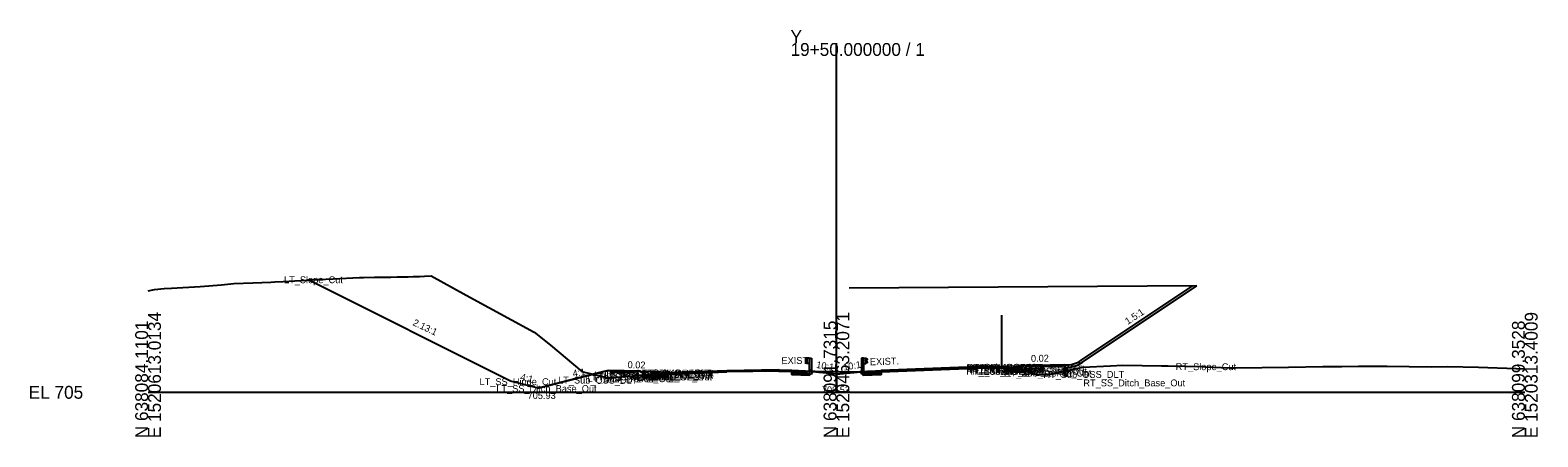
# Model space of a CAD drawing. Extents: x -26 to 303, y -10 to 5039.
# Drawn here: x -25.7 to 302.8, y 2990.3 to 3078.8 of the extents above; entities that cross this region are included whole.
import ezdxf

# ---------------------------------------------------------------- set-up
doc = ezdxf.new("R2010")
doc.units = 0
for name, color, linetype in [('Default', 7, 'Continuous'), ('Exist Cross Section Cell', 7, 'Continuous'), ('Exist XS Center Line Elevation Label', 7, 'Continuous'), ('Exist XS Ground Line', 7, 'Continuous'), ('Prop CMT Bridge Metal Rail', 7, 'Continuous'), ('Prop CMT Pvmt Course 1', 7, 'Continuous'), ('Prop CMT Pvmt Course 2', 7, 'Continuous'), ('Prop CMT Pvmt Course 3', 7, 'Continuous'), ('Prop CMT Pvmt Surface Shoulder', 7, 'Continuous'), ('Prop CMT Shld Paved Course 1', 7, 'Continuous'), ('Prop CMT Shld Paved Course 2', 7, 'Continuous'), ('Prop CMT Shld Paved Course 3', 7, 'Continuous'), ('Prop CMT Slope Grass', 7, 'Continuous'), ('Prop CMT Subgrade Earthwork', 7, 'Continuous'), ('Prop Conc 4in Sidewalk', 7, 'Continuous'), ('Prop XS Ditch Standard Text', 7, 'Continuous'), ('Prop XS Earthwork Shape', 7, 'Continuous'), ('Prop XS SE Text', 7, 'Continuous'), ('Prop XS Side Slope Text', 7, 'Continuous'), ('Scratch_Level_0', 7, 'Continuous'), ('Scratch_Level_1', 7, 'Continuous'), ('Scratch_Level_7', 7, 'Continuous'), ('Typical Curb CELL', 7, 'Continuous'), ('Typical Guardrail CELL', 7, 'Continuous'), ('Typical Shoulder Slope Information CELL', 7, 'Continuous')]:
    doc.layers.add(name, color=color, linetype=linetype)

# ---------------------------------------------------------------- blocks, each defined once
blk = doc.blocks.new('2_6 CURB RIGHT')
at = {"layer": 'Typical Curb CELL'}
for p, q in [((0, -0.58), (0, 0)), ((0, 0), (1.75, -0.07)), ((2, 0.17), (2, 0.18)), ((2.5, 0.42), (2.24, 0.42)), ((2.31, 0.08), (2.33, -0.01)), ((2.46, 0.04), (2.31, 0.08)), ((2.33, -0.01), (2.46, 0.04)), ((2.5, -0.58), (2.5, 0.42)), ((2.5, -0.58), (0, -0.58)), ((0.26, -0.34), (0.35, -0.22)), ((0.38, -0.34), (0.26, -0.34)), ((0.35, -0.22), (0.38, -0.34)), ((1.03, -0.39), (1.09, -0.28)), ((1.19, -0.36), (1.03, -0.39)), ((1.09, -0.28), (1.19, -0.36)), ((1.51, -0.34), (1.6, -0.22)), ((1.63, -0.34), (1.51, -0.34)), ((1.6, -0.22), (1.63, -0.34)), ((2.27, -0.39), (2.34, -0.28)), ((2.44, -0.36), (2.27, -0.39)), ((2.34, -0.28), (2.44, -0.36))]:
    blk.add_line(p, q, dxfattribs=at)
for centre in [(2.27, 0.34), (2.43, 0.12), (2.49, 0.31), (0.01, -0.55), (0.02, -0.25), (0.03, -0.15), (0.07, -0.39), (0.09, -0.18), (0.17, -0.34), (0.2, -0.06), (0.22, -0.58), (0.3, -0.14), (0.34, -0.04), (0.38, -0.51), (0.49, -0.1), (0.52, -0.21), (0.59, -0.53), (0.67, -0.29), (0.69, -0.12), (0.7, -0.45), (0.71, -0.07), (0.76, -0.56), (0.79, -0.26), (0.93, -0.5), (0.97, -0.1), (1.09, -0.15), (1.11, -0.54), (1.26, -0.55), (1.27, -0.25), (1.28, -0.15), (1.32, -0.39), (1.34, -0.18), (1.42, -0.34), (1.45, -0.1), (1.47, -0.58), (1.54, -0.14), (1.63, -0.51), (1.74, -0.1), (1.77, -0.21), (1.84, -0.53), (1.92, -0.29), (1.94, -0.12), (1.95, -0.45), (1.96, -0.07), (2.01, -0.56), (2.04, -0.26), (2.18, -0.5), (2.22, -0.1), (2.34, -0.15), (2.35, -0.54)]:
    blk.add_circle(centre, 0.00802, dxfattribs=at)
for centre, start, end in [((1.76, 0.17), 267.6155, 0), ((2.24, 0.18), 90, 180)]:
    blk.add_arc(centre, 0.24, start, end, dxfattribs=at)

msp = doc.modelspace()

# ---------------------------------------------------------------- linework, layer by layer
at = {"layer": 'Exist Cross Section Cell'}
for p, q in [((150, 3000), (150, 3076.04)), ((0, 3000), (150, 3000)), ((150, 3000), (300, 3000))]:
    msp.add_line(p, q, dxfattribs=at)
at = {"layer": 'Exist XS Ground Line'}
msp.add_lwpolyline([(0, 3022.1), (1.43, 3022.4), (3.51, 3022.57), (5.09, 3022.68), (11.37, 3023.04), (16.02, 3023.41), (18.66, 3023.67), (22.81, 3023.83), (26.72, 3024.01), (27.59, 3024.06), (29.41, 3024.15), (37.09, 3024.58), (40.3, 3024.73), (46.06, 3024.99), (46.46, 3025), (46.96, 3025.02), (49.31, 3025.03), (49.79, 3025.06), (50.16, 3025.06), (50.8, 3025.08), (51.96, 3025.09), (52.93, 3025.1), (54.29, 3025.12), (55.76, 3025.17), (56.68, 3025.17), (57.77, 3025.19), (59.18, 3025.2), (60.21, 3025.25), (61.66, 3025.35), (69.3, 3021.17), (84.1, 3013.07), (87.72, 3010.24), (94.49, 3004.51), (99.34, 3003.34), (100.25, 3003.11), (106.22, 3003.66), (110.41, 3004.05), (111.01, 3004.07), (111.75, 3004.1), (113.02, 3004.16), (113.87, 3004.21), (114.34, 3004.22), (115.53, 3004.26), (116.25, 3004.29), (118.03, 3004.36), (118.63, 3004.39), (120.53, 3004.46), (121, 3004.48), (123.03, 3004.56), (123.73, 3004.59), (125.77, 3004.68), (128, 3004.72), (130.52, 3004.76), (133.17, 3004.8), (135.75, 3004.84), (137.58, 3004.85), (138.16, 3004.85), (140.58, 3004.75), (141.18, 3004.74), (147.46, 3004.56), (150, 3004.53), (153.44, 3004.49), (155.46, 3004.48), (161.42, 3004.79), (162.01, 3004.82), (162.36, 3004.83), (163.11, 3004.86), (164.85, 3004.92), (165.58, 3004.94), (167.48, 3005.02), (168.09, 3005.05), (168.65, 3005.07), (170.59, 3005.13), (171.02, 3005.15), (173.25, 3005.24), (173.89, 3005.27), (175.58, 3005.3), (178.13, 3005.36), (179.44, 3005.38), (180.61, 3005.41), (182.94, 3005.44), (183.25, 3005.45), (185.05, 3005.47), (185.58, 3005.46), (187.15, 3005.37), (189.92, 3005.22), (192.94, 3004.07), (193.72, 3003.8), (194.17, 3003.8), (196.42, 3003.84), (197.48, 3004.07), (203.66, 3005.45), (209.73, 3005.77), (212.4, 3005.89), (220.85, 3005.78), (221.51, 3005.77), (222.28, 3005.75), (229.77, 3005.59), (230.37, 3005.53), (235.69, 3005.3), (236.12, 3005.32), (236.97, 3005.33), (248.53, 3005.48), (255.97, 3005.59), (260.11, 3005.64), (263.74, 3005.7), (264.76, 3005.68), (268.54, 3005.68), (269.98, 3005.72), (279.57, 3005.57), (283.14, 3005.61), (289.93, 3005.44), (298.08, 3005.2), (300, 3005.12)], dxfattribs=at)
at = {"layer": 'Prop CMT Bridge Metal Rail'}
for p, q in [((228.56, 3023.18), (152.76, 3022.7)), ((203.36, 3006.99), (227.65, 3023.18)), ((203.64, 3006.57), (228.56, 3023.18)), ((199.75, 3003.48), (199.75, 3005.98)), ((200.25, 3003.48), (199.75, 3003.48)), ((200.25, 3005.47), (200.25, 3003.48))]:
    msp.add_line(p, q, dxfattribs=at)
for radius, start in [(6, 267.4103), (6.5, 272.0181)]:
    msp.add_arc((200.02, 3011.97), radius, start, 303.8671, dxfattribs=at)
at = {"layer": 'Prop CMT Pvmt Course 1'}
for points in [[(113.25, 3004.18), (113.25, 3003.93)], [(113.25, 3003.93), (113.26, 3003.93)], [(113.26, 3003.93), (113.26, 3004.18)], [(140.25, 3004.49), (140.25, 3004.74)], [(159.75, 3004.49), (159.75, 3004.74)], [(186.74, 3005.16), (186.74, 3005.41)]]:
    msp.add_lwpolyline(points, dxfattribs=at)
at = {"layer": 'Prop CMT Pvmt Course 2'}
for points in [[(113.26, 3003.93), (113.25, 3003.93)], [(113.25, 3003.93), (113.25, 3003.68)], [(113.25, 3003.68), (113.26, 3003.68)], [(113.26, 3003.68), (113.26, 3003.93)], [(140.25, 3004.24), (140.25, 3004.49)], [(159.75, 3004.24), (159.75, 3004.49)]]:
    msp.add_lwpolyline(points, dxfattribs=at)
at = {"layer": 'Prop CMT Pvmt Course 3'}
for points in [[(113.26, 3003.68), (113.25, 3003.68)], [(113.25, 3003.68), (113.25, 3003.3)], [(113.25, 3003.3), (113.26, 3003.3)], [(113.26, 3003.3), (113.26, 3003.68)], [(140.25, 3003.87), (140.25, 3004.24)], [(140.26, 3003.87), (140.25, 3003.87)], [(146, 3004.1), (146.01, 3004.1)], [(159.74, 3003.86), (159.75, 3003.86)], [(159.75, 3003.86), (159.75, 3004.24)]]:
    msp.add_lwpolyline(points, dxfattribs=at)
at = {"layer": 'Prop CMT Pvmt Surface Shoulder'}
for p, q in [((137.45, 3004.86), (143.25, 3004.63)), ((187.75, 3005.37), (182.17, 3005.59))]:
    msp.add_line(p, q, dxfattribs=at)
for points in [[(126.1, 3004.7), (112.25, 3004.14)], [(137.45, 3004.86), (126.1, 3004.7)], [(156.75, 3004.63), (182.17, 3005.59)]]:
    msp.add_lwpolyline(points, dxfattribs=at)
at = {"layer": 'Prop CMT Shld Paved Course 1'}
for p, q in [((137.44, 3004.61), (126.1, 3004.45)), ((137.44, 3004.61), (140.25, 3004.5)), ((143.51, 3004.36), (143.25, 3004.63)), ((156.49, 3004.36), (156.75, 3004.63)), ((159.75, 3004.48), (182.17, 3005.34))]:
    msp.add_line(p, q, dxfattribs=at)
for points in [[(113.87, 3004.21), (112.25, 3004.14)], [(112.25, 3003.89), (113.26, 3003.93)], [(113.25, 3003.93), (113.25, 3004.18)], [(113.26, 3003.93), (126.11, 3004.45)], [(156.75, 3004.63), (162, 3004.82)], [(186.74, 3005.16), (182.17, 3005.34)], [(187.75, 3005.12), (186.74, 3005.16)]]:
    msp.add_lwpolyline(points, dxfattribs=at)
at = {"layer": 'Prop CMT Shld Paved Course 2'}
for p, q in [((143.77, 3004.1), (143.51, 3004.36)), ((156.23, 3004.1), (156.49, 3004.36))]:
    msp.add_line(p, q, dxfattribs=at)
for points in [[(113.26, 3003.93), (112.25, 3003.89)], [(112.25, 3003.64), (113.26, 3003.68)], [(113.25, 3003.68), (113.25, 3003.93)], [(140.25, 3004.5), (143.51, 3004.36)], [(143.77, 3004.1), (140.25, 3004.25)], [(156.23, 3004.1), (159.75, 3004.24)], [(159.75, 3004.49), (156.49, 3004.36)], [(186.74, 3005.16), (187.75, 3005.12)], [(187.75, 3004.87), (186.74, 3004.91)]]:
    msp.add_lwpolyline(points, dxfattribs=at)
at = {"layer": 'Prop CMT Shld Paved Course 3'}
for p, q in [((109.25, 3003.55), (108.82, 3003.13)), ((109.75, 3003.55), (109.25, 3003.55)), ((144.16, 3003.71), (143.77, 3004.1)), ((155.83, 3003.71), (156.23, 3004.1)), ((190.25, 3004.79), (190.75, 3004.79)), ((190.75, 3004.79), (191.18, 3004.36))]:
    msp.add_line(p, q, dxfattribs=at)
for points in [[(108.82, 3003.13), (113.26, 3003.3)], [(113.26, 3003.68), (112.25, 3003.64)], [(113.25, 3003.3), (113.25, 3003.68)], [(140.25, 3004.25), (143.77, 3004.1)], [(144.16, 3003.71), (140.25, 3003.87)], [(155.84, 3003.71), (159.75, 3003.86)], [(159.75, 3004.24), (156.23, 3004.1)], [(186.74, 3004.91), (187.75, 3004.87)], [(191.18, 3004.36), (186.74, 3004.53)]]:
    msp.add_lwpolyline(points, dxfattribs=at)
at = {"layer": 'Prop CMT Slope Grass'}
for p, q in [((84.97, 3000.93), (100.25, 3004.75)), ((100.25, 3004.75), (109.75, 3004.56)), ((150, 3003.95), (143.25, 3004.63)), ((150, 3003.95), (156.75, 3004.63)), ((199.75, 3005.98), (190.25, 3005.79))]:
    msp.add_line(p, q, dxfattribs=at)
msp.add_lwpolyline([(84.97, 3000.93), (78.97, 3002.43), (34.91, 3024.46)], dxfattribs=at)
at = {"layer": 'Prop CMT Subgrade Earthwork'}
for p, q in [((108.82, 3003.13), (107.34, 3004.61)), ((113.26, 3003.3), (113.26, 3004.18)), ((140.25, 3004.75), (140.25, 3003.87)), ((155.83, 3003.71), (155.08, 3004.46)), ((159.75, 3004.74), (159.75, 3003.86)), ((186.74, 3004.53), (186.74, 3005.41)), ((191.18, 3004.36), (192.65, 3005.83)), ((199.75, 3005.98), (199.75, 3004.58))]:
    msp.add_line(p, q, dxfattribs=at)
for points in [[(113.26, 3003.3), (108.82, 3003.13)], [(140.25, 3004.74), (140.25, 3003.87), (140.26, 3003.87)], [(140.25, 3003.87), (144.16, 3003.71)], [(144.16, 3003.71), (144.91, 3004.46)], [(159.75, 3003.86), (155.83, 3003.71)], [(159.75, 3004.74), (159.75, 3003.86), (159.74, 3003.86)], [(186.74, 3004.53), (191.18, 3004.36)]]:
    msp.add_lwpolyline(points, dxfattribs=at)
at = {"layer": 'Prop Conc 4in Sidewalk'}
for p, q in [((100.75, 3004.74), (100.75, 3004.41)), ((100.75, 3004.41), (105.75, 3004.31)), ((105.75, 3004.64), (105.75, 3004.31)), ((194.25, 3005.87), (194.25, 3005.53)), ((199.25, 3005.63), (194.25, 3005.53)), ((199.25, 3005.97), (199.25, 3005.63))]:
    msp.add_line(p, q, dxfattribs=at)
at = {"layer": 'Prop XS Earthwork Shape'}
for points in [[(57.77, 3025.19), (59.18, 3025.2), (60.21, 3025.25), (61.66, 3025.35), (69.3, 3021.17), (84.1, 3013.07), (87.72, 3010.24), (94.49, 3004.51), (96.93, 3003.92), (84.97, 3000.93), (78.97, 3002.43), (34.91, 3024.46), (37.09, 3024.58), (40.3, 3024.73), (46.06, 3024.99), (46.46, 3025), (46.96, 3025.02), (49.31, 3025.03), (49.79, 3025.06), (50.16, 3025.06), (50.8, 3025.08), (51.96, 3025.09), (52.93, 3025.1), (54.29, 3025.12), (55.76, 3025.17), (56.68, 3025.17)], [(100.25, 3003.11), (106.22, 3003.66), (108.12, 3003.83), (107.34, 3004.61), (100.25, 3004.75), (96.93, 3003.92), (99.34, 3003.34)], [(111.01, 3004.07), (111.75, 3004.1), (113.02, 3004.16), (113.26, 3004.17), (113.26, 3003.3), (108.82, 3003.13), (108.12, 3003.83), (110.41, 3004.05)], [(113.26, 3004.17), (113.26, 3004.18), (113.87, 3004.21)], [(123.03, 3004.56), (123.73, 3004.59), (125.77, 3004.68), (128, 3004.72), (130.52, 3004.76), (131.23, 3004.77), (126.1, 3004.7), (113.87, 3004.21), (114.34, 3004.22), (115.53, 3004.26), (116.25, 3004.29), (118.03, 3004.36), (118.63, 3004.39), (120.53, 3004.46), (121, 3004.48)], [(131.23, 3004.77), (133.17, 3004.8), (135.75, 3004.84), (136.39, 3004.84)], [(137.45, 3004.86), (137.58, 3004.85), (136.39, 3004.84)], [(153.44, 3004.49), (155.31, 3004.48), (155.08, 3004.46), (150, 3003.95), (144.91, 3004.46), (143.25, 3004.63), (140.25, 3004.74), (137.58, 3004.85), (138.16, 3004.85), (140.58, 3004.75), (141.18, 3004.74), (147.46, 3004.56), (150, 3004.53)], [(140.25, 3004.74), (140.26, 3003.87), (144.16, 3003.71), (144.91, 3004.46), (143.25, 3004.63)], [(155.08, 3004.46), (155.31, 3004.48), (155.46, 3004.48), (159.75, 3004.71), (159.74, 3003.86), (155.83, 3003.71)], [(173.25, 3005.24), (173.89, 3005.27), (175.58, 3005.3), (178.13, 3005.36), (179.44, 3005.38), (180.61, 3005.41), (182.94, 3005.44), (183.25, 3005.45), (185.05, 3005.47), (185.31, 3005.47), (182.17, 3005.59), (159.75, 3004.74), (159.75, 3004.71), (161.42, 3004.79), (162.01, 3004.82), (162.36, 3004.83), (163.11, 3004.86), (164.85, 3004.92), (165.58, 3004.94), (167.48, 3005.02), (168.09, 3005.05), (168.65, 3005.07), (170.59, 3005.13), (171.02, 3005.15)], [(185.97, 3005.44), (185.31, 3005.47), (185.58, 3005.46)], [(185.97, 3005.44), (186.74, 3005.4), (186.74, 3005.41)], [(189.92, 3005.22), (191.46, 3004.63), (191.18, 3004.36), (186.74, 3004.53), (186.74, 3005.4), (187.15, 3005.37)], [(199.75, 3005.98), (199.75, 3004.58), (197.48, 3004.07), (196.42, 3003.84), (194.17, 3003.8), (193.72, 3003.8), (192.94, 3004.07), (191.46, 3004.63), (192.65, 3005.83)]]:
    msp.add_lwpolyline(points, close=True, dxfattribs=at)
at = {"layer": 'Scratch_Level_1'}
msp.add_line((186.01, 3005.62), (186.01, 3016.81), dxfattribs=at)
at = {"layer": 'Scratch_Level_7'}
msp.add_line((150, 3004.53), (150, 3000), dxfattribs=at)
at = {"layer": 'Typical Guardrail CELL'}
for p, q in [((143.57, 3007.4), (143.28, 3007.2)), ((143.57, 3006.87), (143.28, 3007.07)), ((143.57, 3006.78), (143.28, 3006.57)), ((143.57, 3006.24), (143.28, 3006.45)), ((144.07, 3007.4), (143.57, 3007.4)), ((143.57, 3007.4), (143.57, 3006.24)), ((143.57, 3006.82), (143.57, 3006.87)), ((143.57, 3006.82), (143.57, 3006.78)), ((144.07, 3006.24), (143.57, 3006.24)), ((144.07, 3007.4), (144.07, 3004.92)), ((144.07, 3007.4), (144.57, 3007.4)), ((144.57, 3007.4), (144.57, 3004.92)), ((155.93, 3007.44), (155.43, 3007.44)), ((155.43, 3007.44), (155.43, 3004.96)), ((155.93, 3007.44), (155.93, 3004.96)), ((155.93, 3007.44), (156.43, 3007.44)), ((155.93, 3006.28), (156.43, 3006.28)), ((156.43, 3007.44), (156.43, 3006.28)), ((156.43, 3007.44), (156.72, 3007.24)), ((156.43, 3006.91), (156.72, 3007.11)), ((156.43, 3006.86), (156.43, 3006.91)), ((156.43, 3006.86), (156.43, 3006.82)), ((156.43, 3006.82), (156.72, 3006.61)), ((156.43, 3006.28), (156.72, 3006.48)), ((144.07, 3004.92), (144.57, 3004.92)), ((144.07, 3004.92), (144.07, 3003.91)), ((144.57, 3004.92), (144.57, 3003.91)), ((155.93, 3004.96), (155.43, 3004.96)), ((155.43, 3004.96), (155.43, 3003.95)), ((155.93, 3004.96), (155.93, 3003.95))]:
    msp.add_line(p, q, dxfattribs=at)
for centre, start, end in [((143.33, 3007.14), 125.003, 235.0112), ((143.33, 3006.51), 125.0059, 235.0366), ((156.67, 3007.18), 304.9888, 54.997), ((156.67, 3006.55), 304.9634, 54.9941)]:
    msp.add_arc(centre, 0.0776, start, end, dxfattribs=at)

# ---------------------------------------------------------------- block references
at = {"layer": 'Prop CMT Slope Grass', "yscale": -1, "rotation": 180}
msp.add_blockref('2_6 CURB RIGHT', (112.25, 3004.14), dxfattribs=at)
at = {"layer": 'Prop CMT Slope Grass'}
msp.add_blockref('2_6 CURB RIGHT', (187.75, 3005.37), dxfattribs=at)

# ---------------------------------------------------------------- texts
at = {"layer": 'Default'}
msp.add_text('-', height=0.0001, dxfattribs=at).set_placement((0, 3000))
at = {"layer": 'Exist Cross Section Cell'}
for s, p in [('Y', (140, 3076.04)), ('19+50.000000 / 1', (140, 3073.24)), ('EL 705', (-26, 2998.6))]:
    msp.add_text(s, height=2.8, dxfattribs=at).set_placement(p)
for s, p in [('E 1520613.0134', (2.8, 2990)), ('E 1520463.2071', (152.8, 2990)), ('E 1520313.4009', (302.8, 2990)), ('N 638084.1101', (0, 2990)), ('N 638091.7315', (150, 2990)), ('N 638099.3528', (300, 2990))]:
    msp.add_text(s, height=2.8, rotation=90, dxfattribs=at).set_placement(p)
at = {"layer": 'Exist XS Center Line Elevation Label'}
msp.add_text('709.53', height=1.5, dxfattribs=at).set_placement((146.82, 2999.78))
at = {"layer": 'Prop XS Ditch Standard Text'}
msp.add_text('705.93', height=1.5, dxfattribs=at).set_placement((82.7, 2998.56))
at = {"layer": 'Prop XS SE Text'}
for rotation, p in [(0.8055, (138.02, 3006.12)), (2.1782, (157.31, 3005.86))]:
    msp.add_text('EXIST.', height=1.5, rotation=rotation, dxfattribs=at).set_placement(p)
at = {"layer": 'Prop XS Side Slope Text'}
for s, rotation, p in [('1.5:1', 33.3137, (213.49, 3014.66)), ('2.13:1', 334.7993, (57.54, 3014.67)), ('10:1', 350.5377, (145.51, 3005.32)), ('10:1', 9.4623, (151.61, 3004.72)), ('4:1', 345.9638, (81, 3002.7)), ('4:1', 9.4623, (92.63, 3003.32))]:
    msp.add_text(s, height=1.5, rotation=rotation, dxfattribs=at).set_placement(p)
at = {"layer": 'Scratch_Level_0'}
for s, p in [('LT_Slope_Cut', (29.63, 3023.75)), ('RT_Sub_Out_DLT', (178.37, 3004.69)), ('RT_PV1_PGL_Out', (178.45, 3004.69)), ('RT_PV1_OEOT', (179.72, 3004.69)), ('RT_Slope_Cut', (223.93, 3004.82)), ('LT_SS_Hinge_Cut', (72.23, 3001.56)), ('LT_Sub_OSS_DLT', (89.35, 3001.91)), ('LT_Sub_Trench_Out', (95.74, 3002.21)), ('LT_PS3_Shelf_Out', (96.95, 3002.6)), ('LT_GS_OS_CTL', (97.19, 3003.06)), ('LT_PS3_OEOP', (99.15, 3002.62)), ('LT_PS2_OEOP', (99.41, 3002.88)), ('LT_PS1_OEOP', (99.85, 3003.14)), ('LT_PV2_PGL_Out', (106.36, 3003.21)), ('LT_PV3_PGL_Out', (106.36, 3002.96)), ('LT_Sub_PGL_Out', (106.4, 3002.59)), ('LT_Sub_Out_DLT', (106.49, 3003.46)), ('LT_PV1_PGL_Out', (106.54, 3003.46)), ('LT_PV2_OEOT', (107.61, 3003.21)), ('LT_PV3_OEOT', (107.61, 3002.96)), ('LT_Sub_OEOT', (107.64, 3002.59)), ('LT_PV1_OEOT', (107.79, 3003.46)), ('RT_PV2_PGL_Out', (178.27, 3004.44)), ('RT_PV3_PGL_Out', (178.27, 3004.19)), ('RT_Sub_PGL_Out', (178.31, 3003.81)), ('RT_PV2_OEOT', (179.54, 3004.44)), ('RT_PV3_OEOT', (179.54, 3004.19)), ('RT_Sub_OEOT', (179.57, 3003.81)), ('RT_Sub_Trench_Out', (186.5, 3003.44)), ('RT_PS3_Shelf_Out', (186.93, 3003.83)), ('RT_PS1_OEOP', (187.78, 3004.37)), ('RT_PS2_OEOP', (187.86, 3004.11)), ('RT_PS3_OEOP', (188.12, 3003.85)), ('RT_GS_OS_CTL', (189.12, 3004.29)), ('RT_Sub_OSS_DLT', (195.1, 3003.14)), ('RT_SS_Ditch_Base_Out', (203.81, 3001.29)), ('LT_SS_Ditch_Base_Out', (75.88, 3000.06))]:
    msp.add_text(s, height=1.5, dxfattribs=at).set_placement(p)
at = {"layer": 'Typical Shoulder Slope Information CELL'}
for rotation, p in [(358.8597, (104.48, 3005.26)), (1.1403, (192.4, 3006.61))]:
    msp.add_text('0.02', height=1.5, rotation=rotation, dxfattribs=at).set_placement(p)

doc.saveas('drawing.dxf')
